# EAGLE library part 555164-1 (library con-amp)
AMP connector
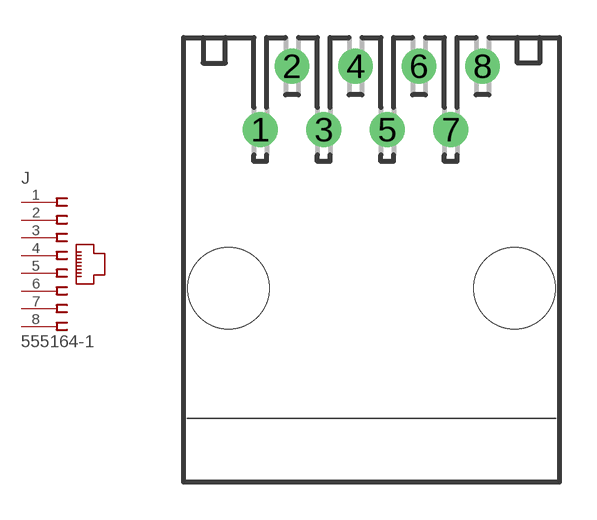
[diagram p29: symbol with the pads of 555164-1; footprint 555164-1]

Designator prefix J

## 555164-1 (MF: TYCO ELECTRONICS; MPN: 5555164-1; OC_FARNELL: 1378887; OC_NEWARK: 42K8761)  [555164-1]
1  1  pas
2  2  pas
3  3  pas
4  4  pas
5  5  pas
6  6  pas
7  7  pas
8  8  pas

## Footprint 555164-1 (pad centres in mm)
Modular Jack without Panel Stops
drill 0.889 round: 1 -4.445,5.207; 2 -3.175,7.747; 3 -1.905,5.207; 4 -0.635,7.747; 5 0.635,5.207; 6 1.905,7.747; 7 3.175,5.207; 8 4.445,7.747
hole 3.251 at -5.715,-1.143
hole 3.251 at 5.715,-1.143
